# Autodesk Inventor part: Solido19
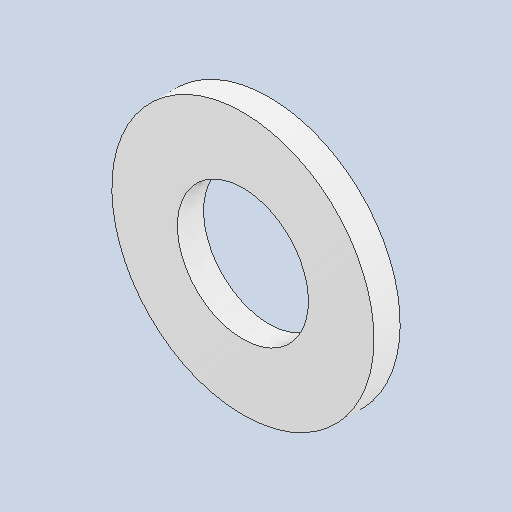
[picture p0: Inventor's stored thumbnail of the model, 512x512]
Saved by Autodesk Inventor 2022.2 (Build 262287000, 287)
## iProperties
Created: 2024-10
Part Number: Solido19
Material: Generico
Document SubType Name: Modeling
Designer: 18907419
Density: 1 g/cm^3
Appearance: Default
Author: 18907419
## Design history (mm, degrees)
feature "Solido19"
node "Solido1"
